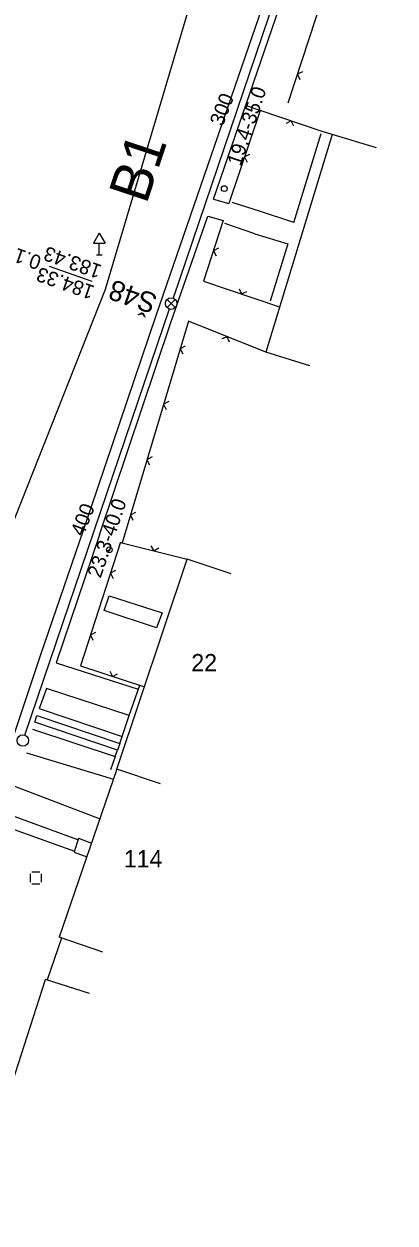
# Model space of a CAD drawing. Extents: x -574526 to -573537, y -1188297 to -1187280.
# Drawn here: x -573878 to -573845.9, y -1187866.3 to -1187762.5 of the extents above; entities that cross this region are included whole.
import ezdxf

# ---------------------------------------------------------------- set-up
doc = ezdxf.new("R2010")
doc.units = 0
for name, color, linetype in [('Vrstva 12', 7, 'Continuous'), ('Vrstva 13', 7, 'Continuous'), ('Vrstva 14', 7, 'Continuous'), ('Vrstva 17', 7, 'Continuous'), ('Vrstva 18', 7, 'Continuous'), ('Vrstva 2', 7, 'Continuous'), ('Vrstva 21', 7, 'Continuous'), ('Vrstva 6', 7, 'Continuous'), ('Vrstva 7', 7, 'Continuous'), ('Vrstva 8', 7, 'Continuous'), ('Vrstva 9', 7, 'Continuous')]:
    doc.layers.add(name, color=color, linetype=linetype)

# ---------------------------------------------------------------- blocks, each defined once
blk = doc.blocks.new('5$270')
at = {"layer": 'Vrstva 6'}
for p, q in [((0, 3.732), (-1, 2)), ((0, 3.732), (1, 2)), ((-1, 2), (1, 2)), ((-0.5, 0), (0.5, 0)), ((0, 0), (0, 2))]:
    blk.add_line(p, q, dxfattribs=at)
blk = doc.blocks.new('6$010')
at = {"layer": 'Vrstva 21'}
blk.add_circle((0, 0), 0.5, dxfattribs=at)
blk = doc.blocks.new('6$091')
at = {"layer": 'Vrstva 21'}
for p, q in [((-1, 0.7), (-1, -0.7)), ((0.7, 1), (-0.7, 1)), ((1, -0.7), (1, 0.7)), ((-0.7, -1), (0.7, -1))]:
    blk.add_line(p, q, dxfattribs=at)

msp = doc.modelspace()

# ---------------------------------------------------------------- linework, layer by layer
at = {"layer": 'Vrstva 13'}
msp.add_line((-573872.14, -1187784.78), (-573875.82, -1187783.49), dxfattribs=at)
at = {"layer": 'Vrstva 17'}
for p, q in [((-573865.63, -1187787.04), (-573864.93, -1187786.34)), ((-573865.63, -1187786.34), (-573864.93, -1187787.04))]:
    msp.add_line(p, q, dxfattribs=at)
at = {"layer": 'Vrstva 2'}
for p, q in [((-573854.18, -1187754.02), (-573865.12, -1187786.22)), ((-573877.97, -1187824.05), (-573865.44, -1187787.16))]:
    msp.add_line(p, q, dxfattribs=at)
at = {"layer": 'Vrstva 6'}
for p, q in [((-573850.27, -1187754.39), (-573855.17, -1187769.33)), ((-573857.58, -1187769.97), (-573858.83, -1187769.53)), ((-573857.58, -1187769.97), (-573860.29, -1187778.03)), ((-573852.19, -1187771.78), (-573857.58, -1187769.97)), ((-573851.34, -1187772.04), (-573852.19, -1187771.78)), ((-573860.77, -1187779.5), (-573862.47, -1187784.76)), ((-573862.47, -1187784.76), (-573855.89, -1187786.97)), ((-573863.78, -1187788.22), (-573869.54, -1187807.4)), ((-573857.09, -1187790.9), (-573863.78, -1187788.22)), ((-573869.68, -1187807.36), (-573873.15, -1187818.06)), ((-573869.68, -1187807.37), (-573863.89, -1187808.81)), ((-573873.15, -1187818.06), (-573867.6, -1187819.87)), ((-573877.82, -1187825.59), (-573870.29, -1187827.85)), ((-573871.48, -1187831.31), (-573878.83, -1187828.51)), ((-573873.32, -1187832.98), (-573873.7, -1187834.19)), ((-573873.32, -1187832.98), (-573872.19, -1187833.4)), ((-573873.7, -1187834.19), (-573872.6, -1187834.59)), ((-573874.79, -1187841.62), (-573876.04, -1187845.24))]:
    msp.add_line(p, q, dxfattribs=at)
for points in [[(-573853.91, -1187766.62), (-573854.35, -1187766.84), (-573854.13, -1187767.28)], [(-573854.66, -1187771.32), (-573854.89, -1187770.88), (-573855.33, -1187771.1)], [(-573858.49, -1187773.78), (-573858.94, -1187774), (-573858.71, -1187774.44)], [(-573861.18, -1187781.9), (-573861.62, -1187782.13), (-573861.39, -1187782.57)], [(-573859.4, -1187785.42), (-573859.18, -1187785.86), (-573858.74, -1187785.64)], [(-573860.24, -1187790.02), (-573860.44, -1187789.56), (-573860.89, -1187789.75)], [(-573864.06, -1187790.38), (-573864.5, -1187790.62), (-573864.27, -1187791.05)], [(-573865.5, -1187795.18), (-573865.94, -1187795.41), (-573865.71, -1187795.85)], [(-573866.94, -1187799.97), (-573867.38, -1187800.21), (-573867.15, -1187800.64)], [(-573868.38, -1187804.77), (-573868.82, -1187805), (-573868.59, -1187805.44)], [(-573867.04, -1187807.67), (-573866.79, -1187808.09), (-573866.36, -1187807.83)], [(-573870.11, -1187809.81), (-573870.55, -1187810.03), (-573870.32, -1187810.48)], [(-573871.84, -1187815.16), (-573872.28, -1187815.39), (-573872.06, -1187815.83)], [(-573870.6, -1187818.52), (-573870.38, -1187818.97), (-573869.93, -1187818.74)]]:
    msp.add_lwpolyline(points, dxfattribs=at)
at = {"layer": 'Vrstva 7'}
for p, q in [((-573851.34, -1187772.04), (-573857.09, -1187790.9)), ((-573847.51, -1187773.21), (-573851.34, -1187772.04)), ((-573853.26, -1187792.07), (-573857.09, -1187790.9)), ((-573870, -1187827.01), (-573863.89, -1187808.81)), ((-573860.1, -1187810.08), (-573863.89, -1187808.81)), ((-573870, -1187827.01), (-573874.99, -1187841.54)), ((-573866.21, -1187828.28), (-573870, -1187827.01)), ((-573871.21, -1187842.84), (-573874.99, -1187841.54)), ((-573882.98, -1187866.29), (-573876.16, -1187845.2)), ((-573872.35, -1187846.43), (-573876.16, -1187845.2))]:
    msp.add_line(p, q, dxfattribs=at)
at = {"layer": 'Vrstva 8'}
for centre in [(-573865.28, -1187786.69), (-573878.13, -1187824.52)]:
    msp.add_circle(centre, 0.5, dxfattribs=at)
at = {"layer": 'Vrstva 9'}
for p, q in [((-573847.2, -1187731.44), (-573866.59, -1187787.67)), ((-573861.63, -1187777.64), (-573845.89, -1187731.9)), ((-573854.65, -1187779.68), (-573852.29, -1187771.96)), ((-573861.63, -1187777.64), (-573860.29, -1187778.03)), ((-573857.54, -1187778.73), (-573860.01, -1187777.95)), ((-573865.34, -1187788.41), (-573862.12, -1187779.11)), ((-573862.12, -1187779.11), (-573860.77, -1187779.5)), ((-573854.65, -1187779.68), (-573857.54, -1187778.73)), ((-573858.04, -1187780.66), (-573860.64, -1187779.77)), ((-573858.04, -1187780.66), (-573855.17, -1187781.52)), ((-573855.17, -1187781.52), (-573856.72, -1187786.48)), ((-573880.84, -1187810.33), (-573870.98, -1187785.45)), ((-573866.59, -1187787.67), (-573872.92, -1187806.34)), ((-573871.5, -1187806.71), (-573865.34, -1187788.41)), ((-573872.92, -1187806.34), (-573876.59, -1187817.11)), ((-573871.5, -1187806.71), (-573875.24, -1187817.79)), ((-573871.09, -1187813.25), (-573870.66, -1187812)), ((-573870.66, -1187812), (-573866.07, -1187813.47)), ((-573866.55, -1187814.75), (-573871.09, -1187813.25)), ((-573866.07, -1187813.47), (-573866.55, -1187814.75)), ((-573876.59, -1187817.11), (-573880.72, -1187829.39)), ((-573875.24, -1187817.79), (-573868.13, -1187820.07)), ((-573868.91, -1187822.36), (-573868.01, -1187819.73)), ((-573876.09, -1187820.01), (-573876.72, -1187821.74)), ((-573868.91, -1187822.36), (-573876.09, -1187820.01)), ((-573876.72, -1187821.74), (-573869.53, -1187824.17)), ((-573877.1, -1187822.94), (-573876.92, -1187822.35)), ((-573876.92, -1187822.35), (-573869.74, -1187824.77)), ((-573869.53, -1187824.17), (-573868.91, -1187822.36)), ((-573877.29, -1187823.55), (-573870.13, -1187825.91)), ((-573869.92, -1187825.34), (-573877.1, -1187822.94)), ((-573869.74, -1187824.77), (-573869.92, -1187825.34)), ((-573869.74, -1187824.77), (-573869.53, -1187824.17)), ((-573870.13, -1187825.91), (-573870.53, -1187827.06)), ((-573870.13, -1187825.91), (-573869.92, -1187825.34)), ((-573873.36, -1187833.11), (-573879.67, -1187830.82)), ((-573880, -1187831.81), (-573873.67, -1187834.09))]:
    msp.add_line(p, q, dxfattribs=at)
msp.add_lwpolyline([(-573870.98, -1187785.45), (-573857.5, -1187740.08), (-573854.75, -1187716.25)], dxfattribs=at)

# ---------------------------------------------------------------- block references
at = {"layer": 'Vrstva 21', "xscale": 0.5, "yscale": 0.5}
for name, p in [('6$010', (-573860.68, -1187776.74)), ('6$010', (-573870.64, -1187808)), ('6$091', (-573877.01, -1187836.42))]:
    msp.add_blockref(name, p, dxfattribs=at)
at = {"layer": 'Vrstva 6', "xscale": 0.5, "yscale": 0.5}
msp.add_blockref('5$270', (-573871.51, -1187782.47), dxfattribs=at)

# ---------------------------------------------------------------- texts
at = {"layer": 'Vrstva 12'}
for s, p in [('22', (-573863.54, -1187818.53)), ('114', (-573869.39, -1187835.51))]:
    msp.add_text(s, height=1.5, dxfattribs=at).set_placement(p)
at = {"layer": 'Vrstva 13'}
for s, p in [('0.166', (-573876.43, -1187782.63)), ('183.43', (-573871.21, -1187783.4)), ('184.33', (-573871.84, -1187785.2))]:
    msp.add_text(s, height=1.25, rotation=160.6756, dxfattribs=at).set_placement(p)
at = {"layer": 'Vrstva 14'}
for s, height, rotation, p in [('300', 1.25, 68.7959, (-573860.82, -1187771.4)), ('19.4-35.0', 1.25, 71.239, (-573859.28, -1187774.86)), ('B1', 3.5, 71.5717, (-573867.43, -1187778.16)), ('400', 1.25, 68.7959, (-573872.88, -1187806.91)), ('23.3-40.0', 1.25, 71.239, (-573871.4, -1187810.53))]:
    msp.add_text(s, height=height, rotation=rotation, dxfattribs=at).set_placement(p)
at = {"layer": 'Vrstva 18'}
msp.add_text('Š48', height=1.75, rotation=160.6756, dxfattribs=at).set_placement((-573866.36, -1187785.96))

doc.saveas('drawing.dxf')
